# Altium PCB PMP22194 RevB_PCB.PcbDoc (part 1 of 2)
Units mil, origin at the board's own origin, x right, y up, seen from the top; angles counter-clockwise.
Board outline 2100 x 2100 mil, 4 copper layers (Top Layer, Signal Layer 1, Signal Layer 2, Bottom Layer), stack 62.2 mil thick; 70 components, 29 nets, 172 pads, 172 vias.
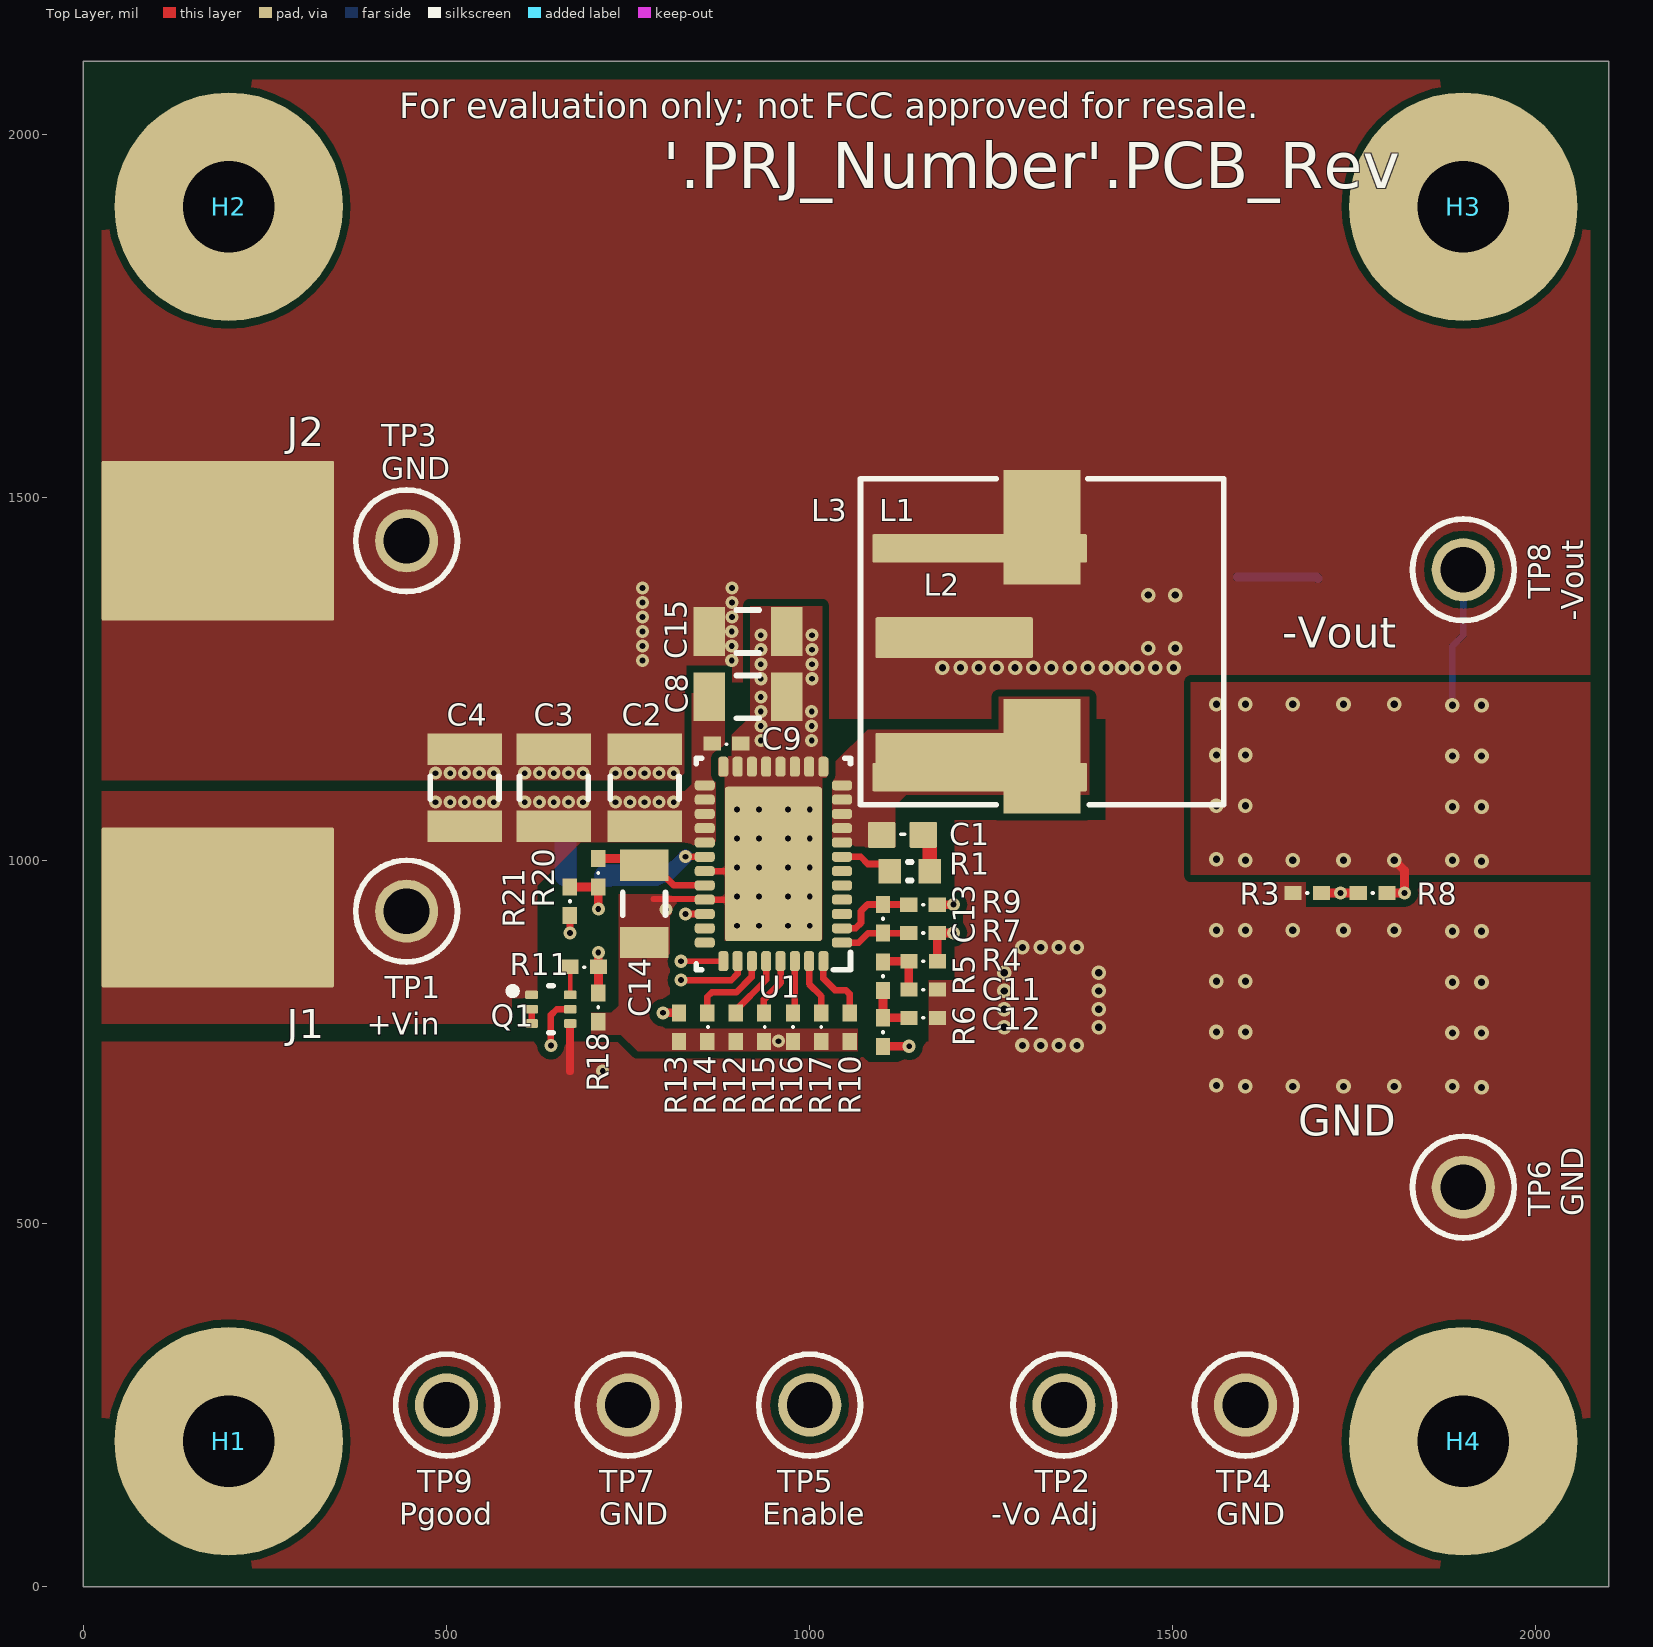
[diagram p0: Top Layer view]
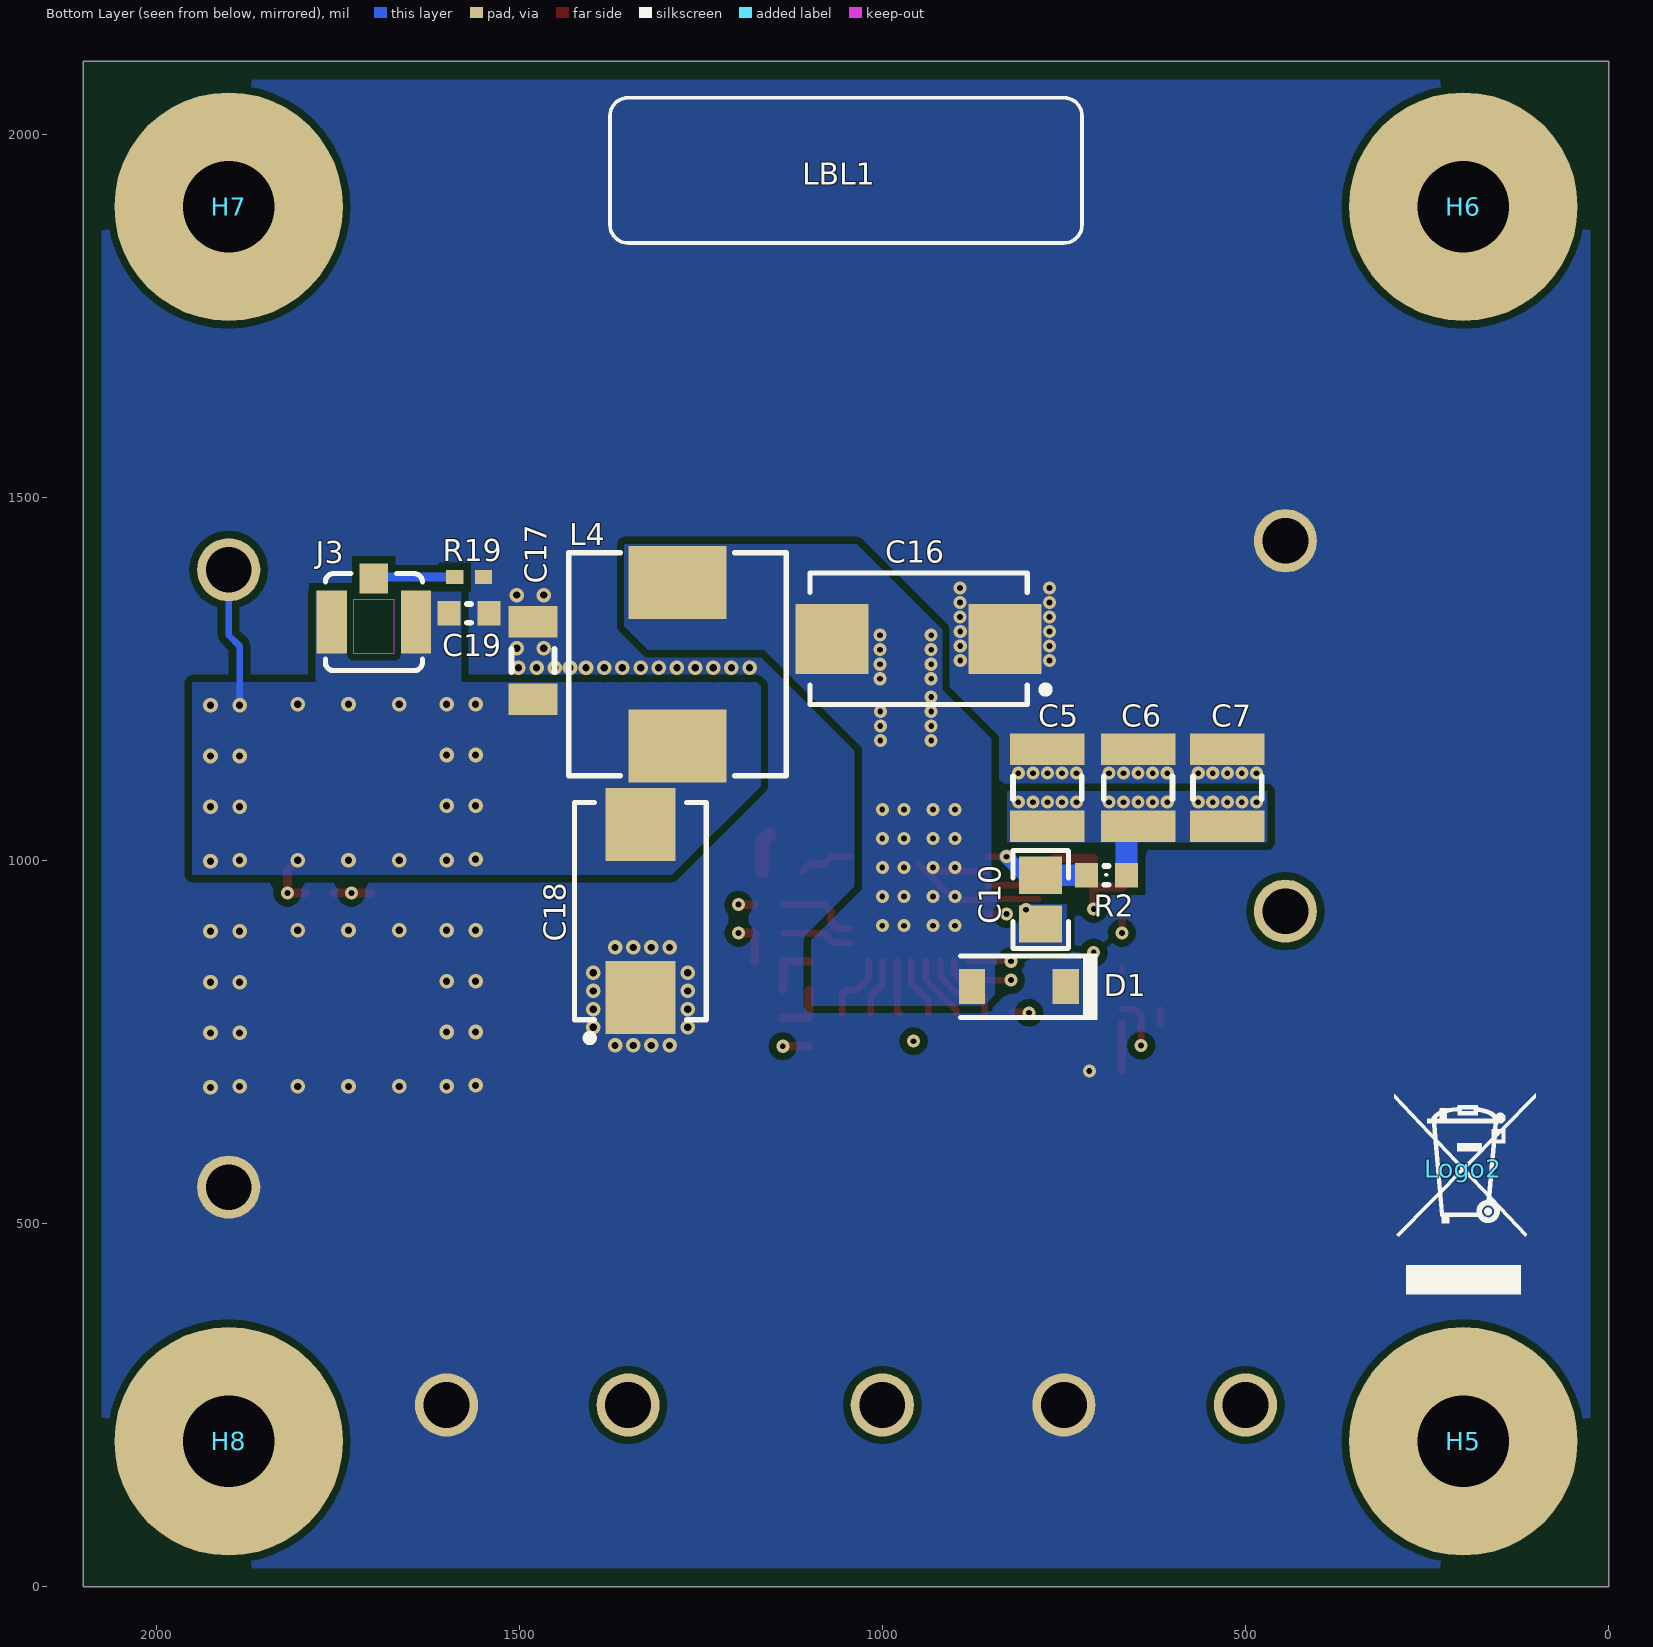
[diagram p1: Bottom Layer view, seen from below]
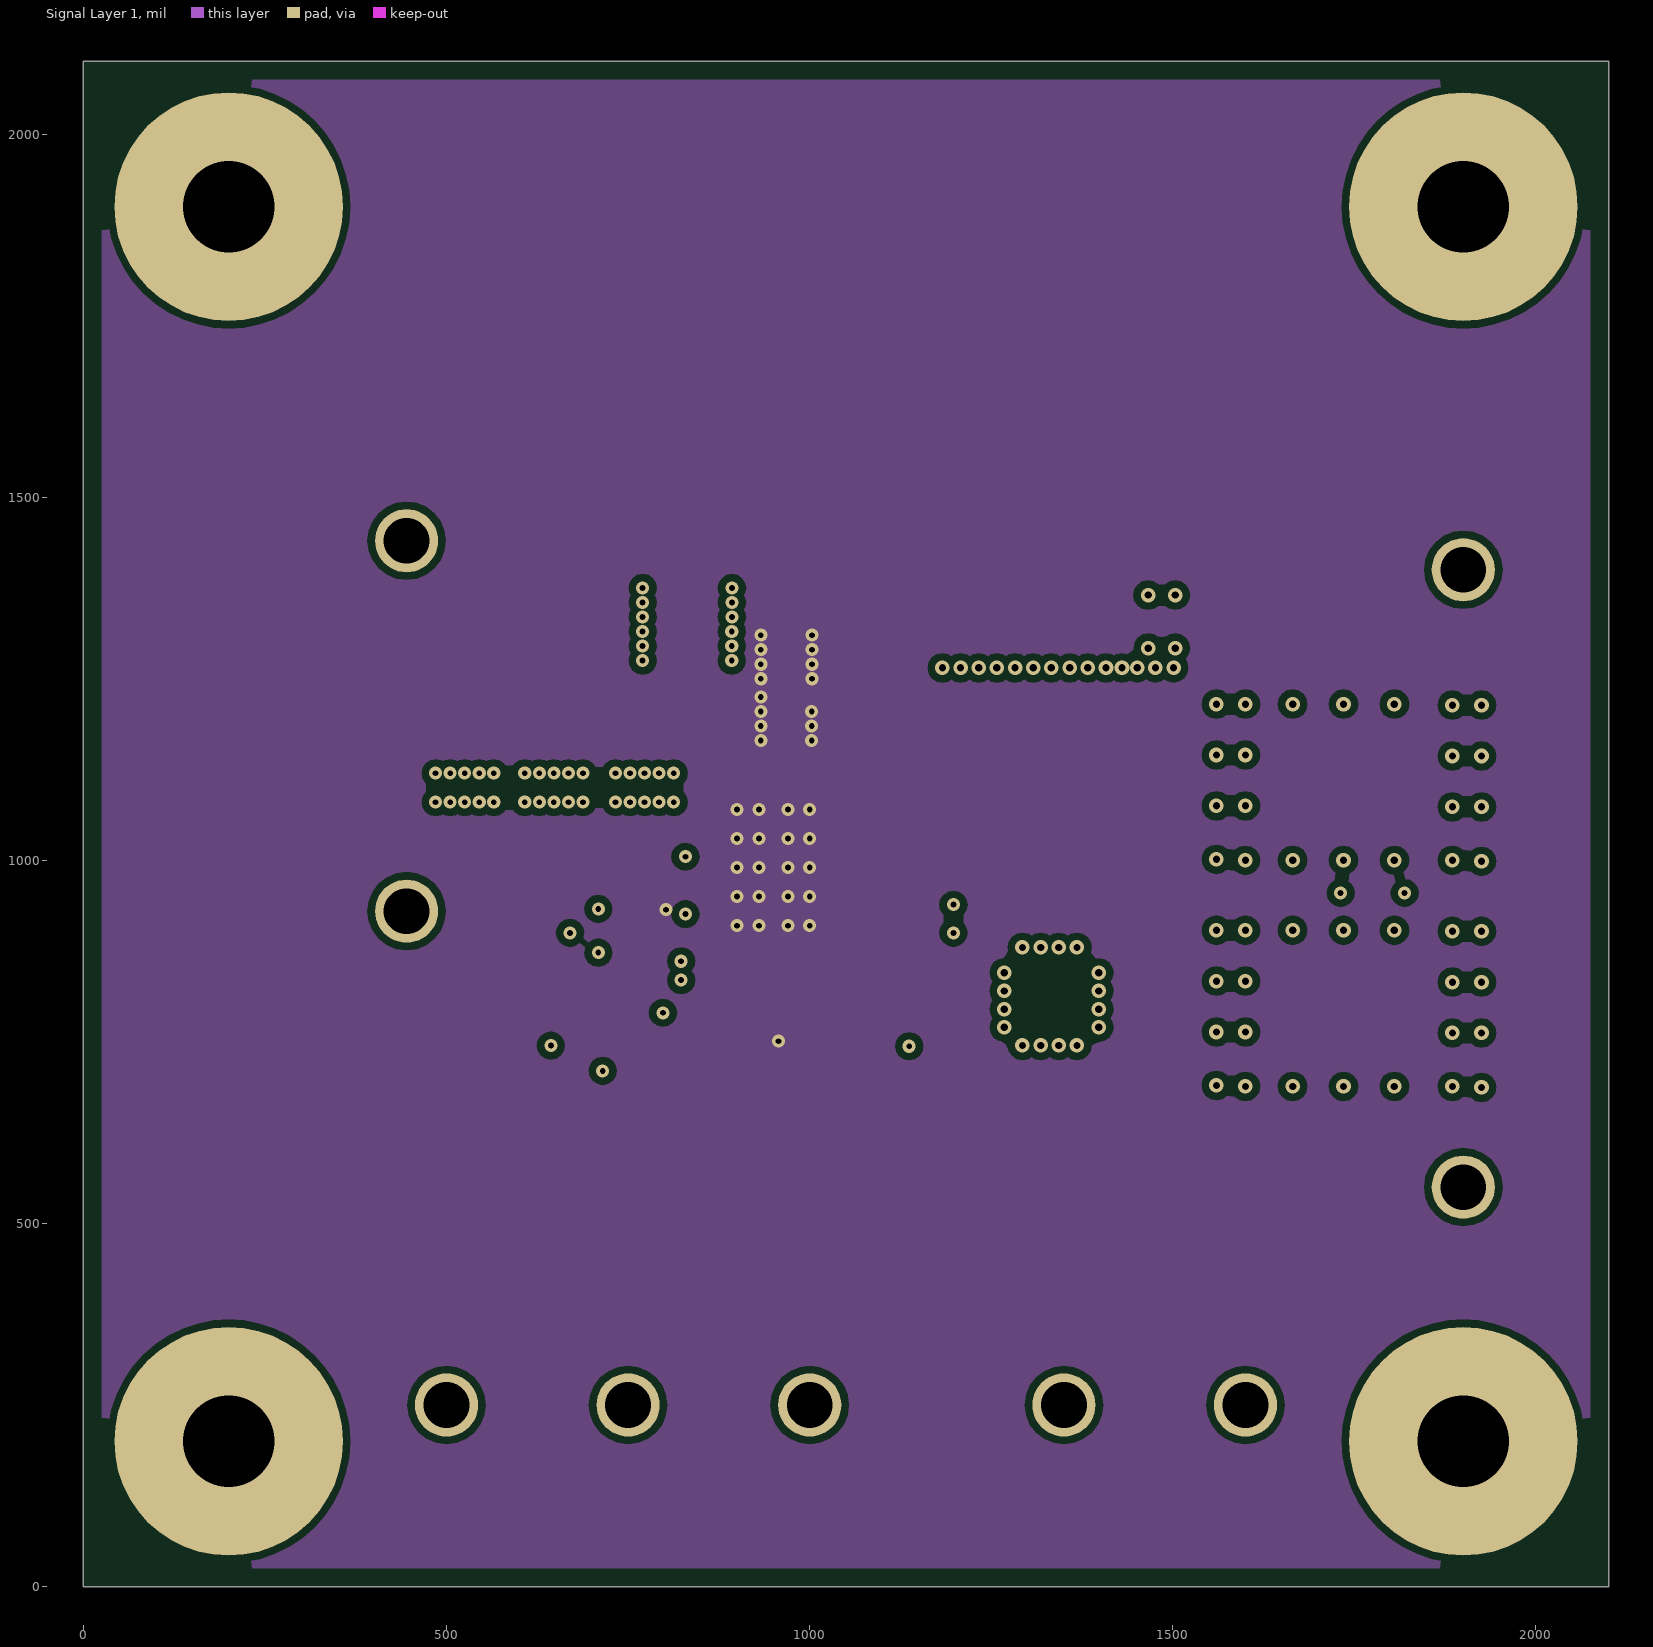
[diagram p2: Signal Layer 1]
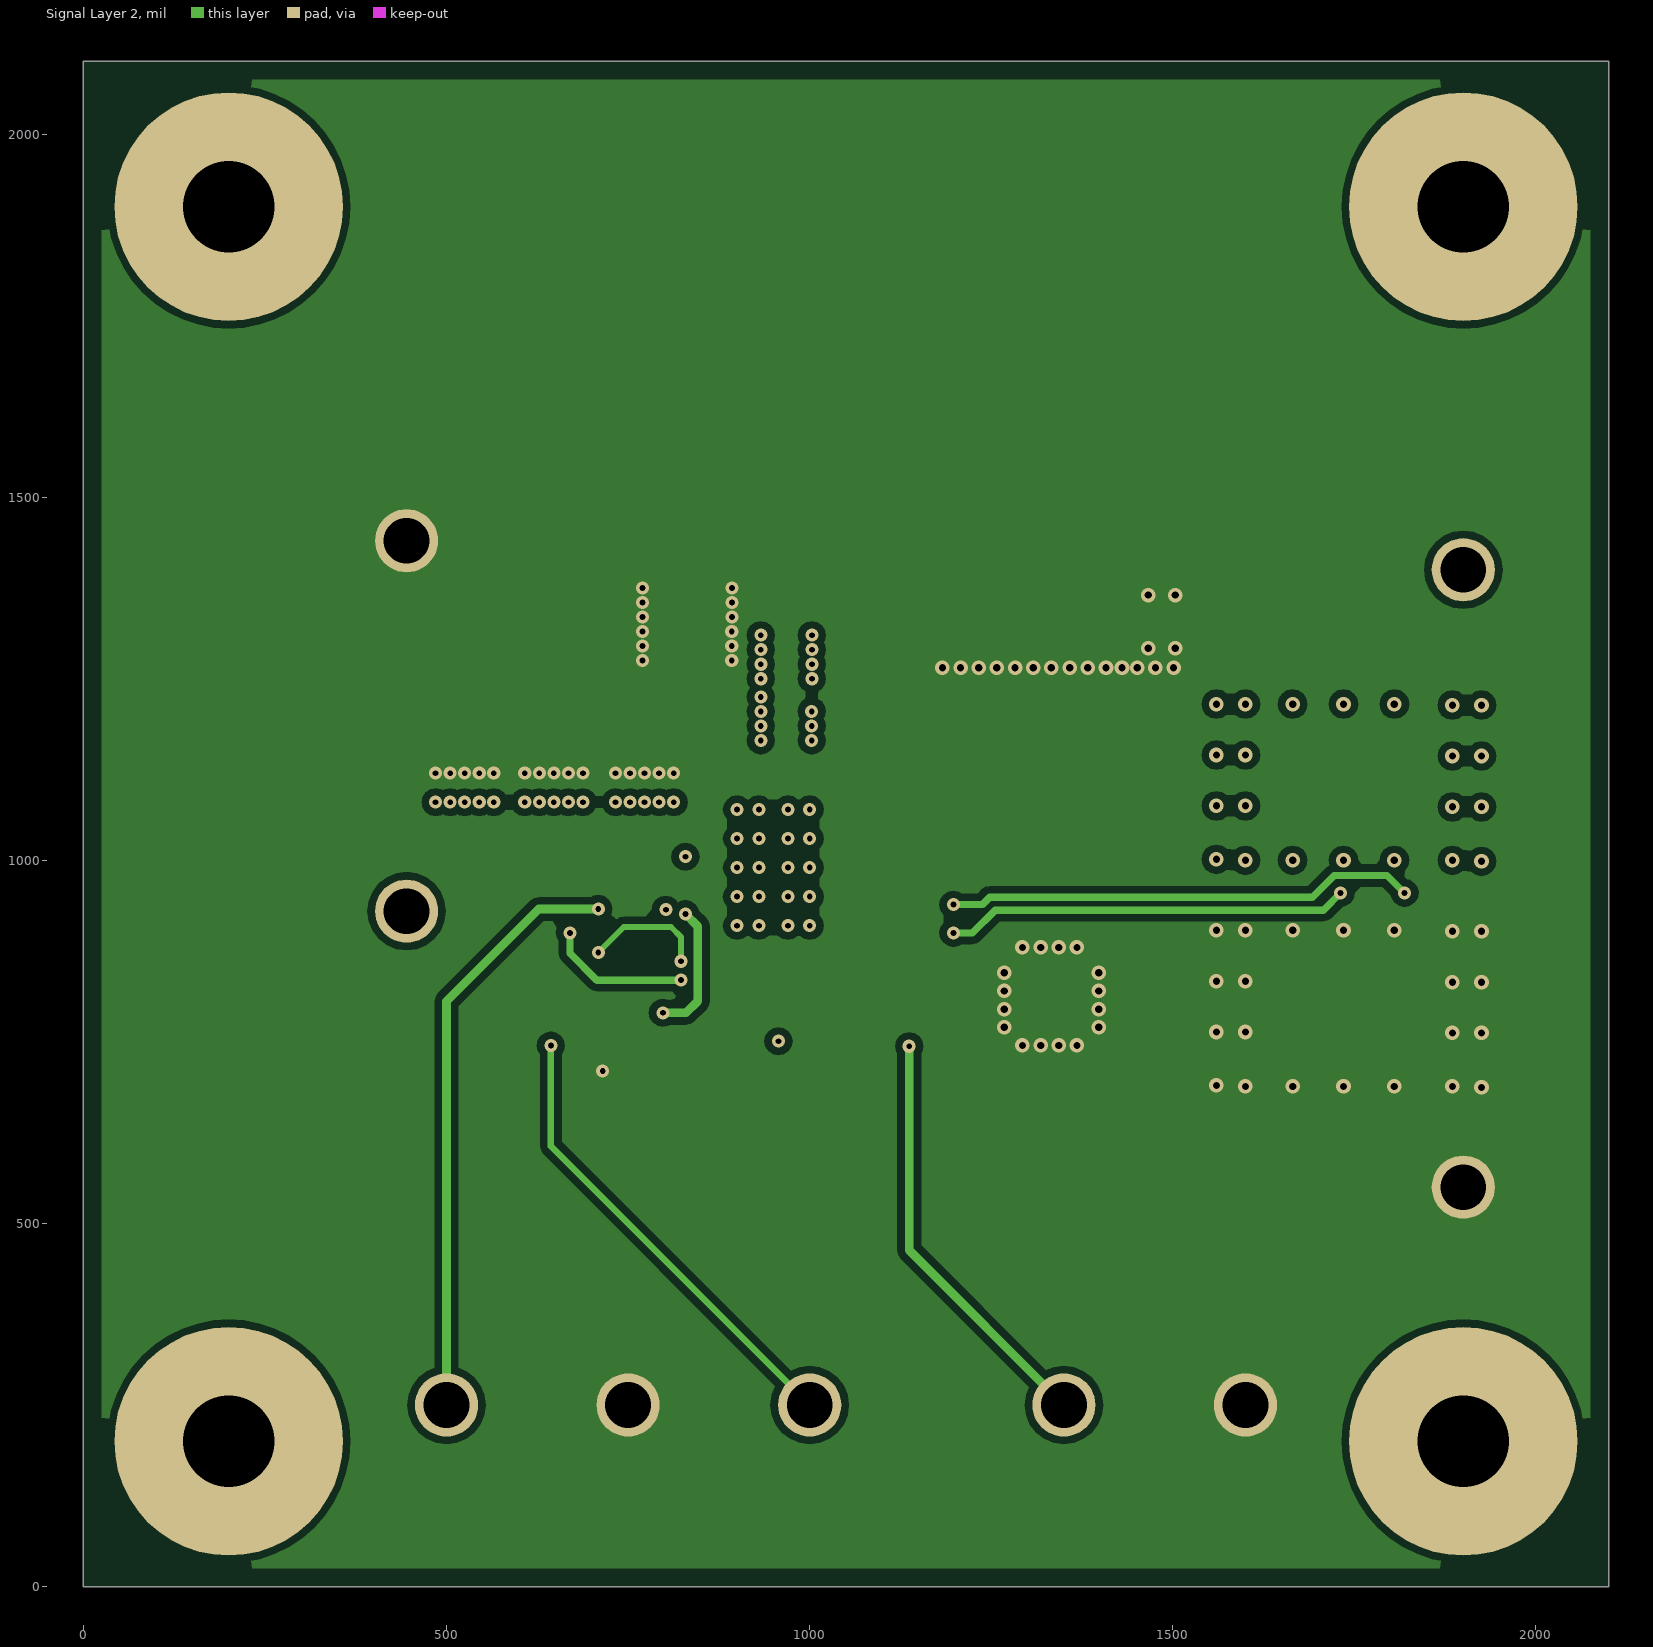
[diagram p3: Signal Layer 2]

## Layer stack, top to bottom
Top Solder: solder mask 0.4, Solder Resist, Dk 3.5
Top Layer: signal copper 2.8
Dielectric 1: dielectric 8, Dk 4.2
Signal Layer 1: signal copper 2.8
Dielectric2: core 35, FR-4, Dk 4.8
Signal Layer 2: signal copper 2.8
Dielectric 3: dielectric 8, Dk 4.2
Bottom Layer: signal copper 2.8
Bottom Solder: solder mask 0.4, Solder Resist, Dk 3.5

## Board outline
0,0 2100,0 2100,2100 0,2100

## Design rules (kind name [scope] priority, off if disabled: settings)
AcuteAngle [All] p1: minimum=4.50000000000000E+0001 checktracksonly=FALSE
AssemblyTestPointUsage [All] p1: valid=2
BoardOutlineClearance BoardOutlineClearance_MountingHoles [OnCopper and InComponentClass('Mounting Holes')] p1: gap=39.37 ignorepadtopadclearanceinfootprint=FALSE
BoardOutlineClearance BoardOutlineClearance_Poly [OnCopper and IsPoly] p2: gap=25 ignorepadtopadclearanceinfootprint=FALSE
BoardOutlineClearance [OnCopper and Not InComponentClass('Logo') and not InComponentClass('FiducialMark') and not InRegion(1000,500,4000,800) and not InPoly] p3: gap=25 ignorepadtopadclearanceinfootprint=FALSE
Clearance Clearance_Keepouts [((IsTrack Or IsArc) And Not InPoly) And IsFree and IsKeepOut vs ((IsTrack Or IsArc) And Not InPoly) And IsFree and IsKeepOut] p1: gap=0 ignorepadtopadclearanceinfootprint=FALSE
Clearance Clearance_Poly [InPolygon] p2: gap=10 ignorepadtopadclearanceinfootprint=TRUE
Clearance Clearance_FiducialMark [IsKeepOut and InComponentClass('FiducialMark') vs IsPad and InComponentClass('FiducialMark')] p3: gap=0 ignorepadtopadclearanceinfootprint=FALSE
Clearance [All] p4: gap=7.87 ignorepadtopadclearanceinfootprint=TRUE
ComponentClearance ComponentClearance_Inductors [(InComponent('L1') OR InComponent('L2') OR InComponent('L3')) vs (InComponent('L1') OR InComponent('L2') OR InComponent('L3'))] p1: gap=-1 collisioncheckmode=3 verticalgap=100000 showdistances=FALSE
ComponentClearance ComponentClearance_MountingHoles_FiducialMarks [InComponentClass('Mounting Holes') vs InComponentClass('FiducialMark')] p2: gap=50 collisioncheckmode=3 verticalgap=10 showdistances=FALSE
ComponentClearance ComponentClearance_Shunt [InComponentClass('Header') vs InComponentClass('Shunt')] p3: gap=0 collisioncheckmode=3 verticalgap=0 showdistances=FALSE
ComponentClearance ComponentClearance_Logo [InComponentClass('Logo')] p4: gap=50 collisioncheckmode=3 verticalgap=10 showdistances=FALSE
ComponentClearance ComponentClearance_ScrewToNut [(HasFootprint('NY PMS 440 0025 PH')) vs (HasFootprint('Keystone_1902C'))] p5: gap=5 collisioncheckmode=3 verticalgap=10 showdistances=FALSE
ComponentClearance ComponentClearance_MountingHoles [InComponentClass('Mounting Holes')] p6: gap=50 collisioncheckmode=3 verticalgap=100000 showdistances=FALSE
ComponentClearance ComponentClearance_SmallPassives [HasFootprint('0201*') or HasFootprint('0402*') or HasFootprint('0508') or HasFootprint('0603*') or HasFootprint('0612') or HasFootprint('0805*') or HasFootprint('0815*') or HasFootprint('0830*') or HasFootprint('1206*') or HasFootprint('1210*') or HasFootprint('1808*') or HasFootprint('1812*') or HasFootprint('1825*') or HasFootprint('2010*') or HasFootprint('2220*') or HasFootprint('2225*') or HasFootprint('2512*') or HasFootprint('2728*') or HasFootprint('3518*') vs HasFootprint('0201*') or HasFootprint('0402*') or HasFootprint('0508') or HasFootprint('0603*') or HasFootprint('0612') or HasFootprint('0805*') or HasFootprint('0815*') or HasFootprint('0830*') or HasFootprint('1206*') or HasFootprint('1210*') or HasFootprint('1808*') or HasFootprint('1812*') or HasFootprint('1825*') or HasFootprint('2010*') or HasFootprint('2220*') or HasFootprint('2225*') or HasFootprint('2512*') or HasFootprint('2728*') or HasFootprint('3518*')] p7: gap=14.96 collisioncheckmode=3 verticalgap=10 showdistances=FALSE
ComponentClearance ComponentClearance_THtoSMT [IsThruComponent vs IsSMTComponent] p8: gap=40 collisioncheckmode=3 verticalgap=30 showdistances=FALSE
ComponentClearance ComponentClearance_THtoTH [IsThruComponent vs IsThruComponent] p9: gap=30 collisioncheckmode=3 verticalgap=30 showdistances=FALSE
ComponentClearance [All] p10: gap=15 collisioncheckmode=3 verticalgap=10 showdistances=FALSE
DiffPairsRouting [All] p1: maxlimit=100 minlimit=10 mostfreqgap=10 toplayer_minwidth=15 toplayer_maxwidth=15 toplayer_prefwidth=15 midlayer1_minwidth=15 midlayer1_maxwidth=15 midlayer1_prefwidth=15 midlayer2_minwidth=15 midlayer2_maxwidth=15 midlayer2_prefwidth=15 bottomlayer_minwidth=15 bottomlayer_maxwidth=15 bottomlayer_prefwidth=15 maxuncoupledlength=1000
FabricationTestPointUsage TestPointUsage [All] p1: valid=2 allowmultiple=FALSE
FabricationTestpoint Testpoint [All] p1: side=3 testpointundercomponent=TRUE minsize=40 maxsize=100 preferedsize=60 minholesize=0 maxholesize=40 preferedholesize=32 testpointgrid=1 allowsidetop=TRUE allowsidebottom=TRUE usegrid=TRUE gridtolerance=0.01
FanoutControl Fanout_LCC [IsLCC] p1: bgadir=Out bgaviamode=Centered fanoutstyle=Auto fanoutdirection=Alternating viagrid=1 // Fanout_LCC (Default Rule)
FanoutControl Fanout_BGA [IsBGA] p2: bgadir=Out bgaviamode=Centered fanoutstyle=Auto fanoutdirection=Alternating viagrid=1 // Fanout_BGA (Default Rule)
FanoutControl Fanout_Default [All] p4: bgadir=Out bgaviamode=Centered fanoutstyle=Auto fanoutdirection=Alternating viagrid=1 // Fanout_Default (Default Rule)
FanoutControl Fanout_Small [(CompPinCount < 5)] p5: bgadir=Out bgaviamode=Centered fanoutstyle=Auto fanoutdirection=OutThenIn viagrid=1 // Fanout_Small (Default Rule)
HoleSize [All] p1: absolutevalues=TRUE maxlimit=251 minlimit=7.87 maxpercent=80.000 minpercent=20.000
MinimumAnnularRing MinimumAnnularRing_ThermalPadVias [IsVia and InAnyComponent] p1: minimumring=5
MinimumAnnularRing [All] p2: minimumring=5
MinimumSolderMaskSliver MinimumSolderMaskSliver_Logo [InComponentClass('Logo') vs InComponentClass('Logo')] p1: minsoldermaskwidth=0.7
MinimumSolderMaskSliver [All] p2: minsoldermaskwidth=3.94
PlaneConnect [All] p1: planeconnectstyle=Direct reliefexpansion=10 reliefentries=4 reliefconductorwidth=10 reliefairgap=10
PolygonConnect [All] p1: connectstyle=Direct reliefconductorwidth=10 reliefentries=4 polygonreliefangle="90 Angle" airgapwidth=10
RoutingVias ThermalPadVias [IsVia and InAnyComponent] p1: holewidth=7.87 width=19.68 viastyle="Through Hole" minholewidth=7.87 minwidth=18 maxholewidth=12.99 maxwidth=24
RoutingVias [All] p2: holewidth=16 width=34 viastyle="Through Hole" minholewidth=7.87 minwidth=18 maxholewidth=40 maxwidth=65
SilkToBoardRegionClearance [Not ((IsComment or IsDesignator) And (Hide <> 'False')) and not InRegion(1000,500,4000,800)] p1:
SilkToSilkClearance SilkToSilkClearance_Pb-FreeLogo [(HasFootprint('Pb-Free_Overlay_Medium') OR HasFootprint('Pb-Free_Overlay_Small')) vs (HasFootprint('Pb-Free_Overlay_Medium') OR HasFootprint('Pb-Free_Overlay_Small'))] p1: silktosilkclearance=0
SilkToSilkClearance [All] p2: silktosilkclearance=3.94
SilkToSolderMaskClearance SilkToComponentPadClearance [(IsPad or IsFill or IsRegion) and InAnycomponent] p1: minsilkscreentomaskgap=3 clearancetoexposedcopper=TRUE
SilkToSolderMaskClearance "Silk to Solder Mask Opening" [All] p2: minsilkscreentomaskgap=3 clearancetoexposedcopper=FALSE
SolderMaskExpansion [All] p1: expansion=1.97
UnRoutedNet [All] p1: checkbadconnections=TRUE
Width [All] p1: maxlimit=100 minlimit=6 preferedwidth=10 checkconnectedcopper=TRUE
14 further rules are at their usual default settings.

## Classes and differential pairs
component class "Mounting Holes": H1 H2 H3 H4
component class "PMP22194 RevB_BlankSheet": C1 C2 C3 C4 C5 C6 C7 C8 C9 C10 C11 C12 C13 C14 C15 C16 C17 C18 C19 D1 J1 J2 J3 L1 L2 L3 L4 Q1 R1 R2 R3 R4 R5 R6 R7 R8 R9 R10 R11 R12 R13 R14 R15 R16 R17 R18 R19 R20 R21 TP1 TP2 TP3 TP4 TP5 TP6 TP7 TP8 TP9 U1
component class "PMP22194 RevB_Hardware": H1 H2 H3 H4 H5 H6 H7 H8 LBL1 Logo1 Logo2
component class Label: LBL1

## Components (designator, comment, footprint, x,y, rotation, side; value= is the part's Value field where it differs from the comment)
C1 "CL10B104KB8NNNC" FP-CL10B104KB8NNNC_0603-IPC_B 1127.72,1035 r0 top
C2 "CL32B226KAJNFNE" 1210_270L 772.72,1100 r90 top value=22uF
C3 "CL32B226KAJNFNE" 1210_270L 647.72,1100 r90 top value=22uF
C4 "CL32B226KAJNFNE" 1210_270L 525,1100 r90 top value=22uF
C5 "CL32B226KAJNFNE" 1210_270L 772.72,1100 r90 bottom value=22uF
C6 "CL32B226KAJNFNE" 1210_270L 647.72,1100 r90 bottom value=22uF
C7 "CL32B226KAJNFNE" 1210_270L 525,1100 r90 bottom value=22uF
C8 "CL31B475KAHNFNE" C1206 915,1225 r0 top value=4.7uF
C9 "GCM155R71H104KE02D" 0402L 885.5,1160.72 r0 top value=0.1uF
C10 "CL21B105KBFNNNG" 0805 782,946 r270 bottom value=1uF
C11 "CL05B224KO5NNNC" 0402L 1156.5,822 r0 top value=0.22uF
C12 "CL05B224KO5NNNC" 0402L 1156.5,783 r0 top value=0.22uF
C13 "DNP" 0402L 1101,919.5 r90 top value=1000pF
C14 "CL31B475KAHNFNE" C1206 772,940 r270 top value=4.7uF
C15 "GRM31CR60J107KE39L" C1206 915,1315 r0 top value=100uF
C16 "2R5TPE470M9" 7343-20 950,1305 r0 bottom value=470uF
C17 "GRM31CR60J107KE39L" C1206 1481,1275.15 r270 bottom value=100uF
C18 "2R5TPE470M9" 7343-20 1333,930.09 r90 bottom value=470uF
C19 "CL10B102KB8NNNC" 0603L 1569,1340 r0 bottom value=1000pF
D1 "MBR0540T1G" SOD-123 812,826 r0 bottom value=40V
H1 "NY PMS 440 0025 PH" "NY PMS 440 0025 PH" 200,200 r0 top
H2 "NY PMS 440 0025 PH" "NY PMS 440 0025 PH" 200,1900 r0 top
H3 "NY PMS 440 0025 PH" "NY PMS 440 0025 PH" 1900,1900 r0 top
H4 "NY PMS 440 0025 PH" "NY PMS 440 0025 PH" 1900,200 r0 top
H5 "1902C" Keystone_1902C 200,200 r180 bottom
H6 "1902C" Keystone_1902C 200,1900 r180 bottom
H7 "1902C" Keystone_1902C 1900,1900 r180 bottom
H8 "1902C" Keystone_1902C 1900,200 r180 bottom
J1 "+Vin" Cinch_108-0902-001 0,935 r0 top
J2 "GND" Cinch_108-0903-001 0,1440 r0 top
J3 "-Vout" CONN_UFL-R-SMT-1 1700,1328 r270 bottom
L1 "XAR7030-501MEB" XAR7030 1234,1272 r90 top value=500nH
L2 "XEL6030-471MEB" XEL6030_320 1199,1227 r90 top value=470nH
L3 "MLC1240-451MLB" MLC1240 1320,1301 r90 top value=450nH
L4 "SLC7649S-360KLB" SLC7649 1282,1270 r270 bottom value=36nH
LBL1 "THT-14-423-10" Label_650x200 1050,1950 r180 bottom
Logo1 "FCC disclaimer" FCC_disclaimer 2405,2160 r0 top
Logo2 "WEEE logo" WEEE_Minimum 200,575 r180 bottom
Q1 "RN4907FE,LF(CT" FP-RN4907FE,LF(CT_SOT-6-MFG 643.72,795 r0 top value=-50/50V
R1 "CRCW06032R00FKEA" 0603L 1137.72,985 r0 top value=2.00
R2 "RC0603JR-070RL" 0603L 691.5,979.28 r180 bottom value=0
R3 "CRCW0402665RFKED" 0402L 1685,955 r180 top value=665
R4 "CRCW04021K58FKED" 0402L 1156.22,861 r180 top value=1.58k
R5 "CRCW04021K58FKED" 0402L 1101,840.5 r270 top value=1.58k
R6 "CRCW04021K58FKED" 0402L 1101,763.5 r270 top value=1.58k
R7 "RC0402JR-070RL" 0402L 1156,900 r180 top value=0
R8 "CRCW0402249KFKED" 0402L 1775,955 r180 top value=249k
R9 "RC0402JR-070RL" 0402L 1156,939 r180 top value=0
R10 "RC0402JR-070RL" 0402L 1055,770 r90 top value=0
R11 "CRCW0402100KJNED" 0402L 689.5,853.28 r180 top value=100k
R12 "RC0402JR-070RL" 0402L 898,770 r90 top value=0
R13 "RC0402JR-070RL" 0402L 820,770 r90 top value=0
R14 "DNP" 0402L 859,770 r90 top value=0
R15 "CRCW0402475KFKED" 0402L 937,770 r270 top value=475k
R16 "CRCW0402130KFKED" 0402L 977,770 r90 top value=130k
R17 "RC0402JR-070RL" 0402L 1016,770 r90 top value=0
R18 "CRCW040251K0JNED" 0402L 708.72,797.5 r90 top value=51k
R19 "RC0402FR-0749R9L" 0402L 1569,1390 r0 bottom value=49.9
R20 "CRCW0402100KFKED" 0402L 709,982.72 r90 top value=100k
R21 "CRCW040212K1FKED" 0402L 669.72,943.5 r90 top value=12.1k
TP1 "+Vin" Keystone5010 445,930 r0 top
TP2 "-Vo Adj" Keystone5012 1350,250 r0 top
TP3 "GND" Keystone5011 445,1440 r0 top
TP4 "GND" Keystone5011 1600,250 r0 top
TP5 "Enable" Keystone5012 1000,250 r0 top
TP6 "GND" Keystone5011 1900,550 r90 top
TP7 "GND" Keystone5011 750,250 r0 top
TP8 "-Vout" Keystone5013 1900,1400 r90 top
TP9 "Pgood" Keystone5012 500,250 r0 top
U1 "TPS543B20RVFT" RVF0040A_SMD_NV 950,995 r180 top

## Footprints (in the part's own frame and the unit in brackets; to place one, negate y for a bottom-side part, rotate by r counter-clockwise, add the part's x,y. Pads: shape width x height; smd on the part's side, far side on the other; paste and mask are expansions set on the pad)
0402L [mm] "0402 from SM-752 data"
  rect 0.6x0.5 smd: 1(-0.5,0) 2(0.5,0)
  body extent -0.55,-0.3 0.55,0.3, height 0.6
0603L [mm] "0603 from SM-752 data"
  rect 0.8x0.85 smd: 1(-0.7,0) 2(0.7,0)
  silkscreen extent -0.07,-0.33 0.07,0.33, body extent -0.87,-0.47 0.87,0.47, height 1
0805 [mm] "0805 from SM-752 data"
  rect 1.3x1.5 smd: 1(-0.85,0) 2(0.85,0)
  silkscreen extent -1.72,-0.97 1.72,0.97, body extent -1.1,-0.72 1.1,0.72, height 1.45
1210_270L [mm] "1210"
  rect 1.1x2.6 smd: 1(-1.35,0) 2(1.35,0)
  silkscreen extent -0.4,-1.2 0.4,1.2, body extent -1.7,-1.35 1.7,1.35, height 2.7
7343-20 [mm] "Medium density IPC, based on Kemet case V from T495 datasheet"
  rect 2.55x2.45 smd: 1(-3.025,0) 2(3.025,0)
  silkscreen extent -4.56,-2.3 3.8,2.3, body extent -3.8,-2.3 3.8,2.3, height 2
C1206 [mm] "Chip Capacitor, Body 3.2x1.6mm, IPC High Density"
  rect 1.1x1.7 smd: 1(-1.35,0) 2(1.35,0)
  silkscreen extent -0.4,-0.75 0.4,0.75, body extent -1.7,-0.9 1.7,0.9, height 1.3
Cinch_108-0902-001 [mil] "Banana Jack Insul Nylon Red, TH"
  rrect2% 320x220 smd: 1(185,0)
  body extent -666,-219 272,219, height 232
Cinch_108-0903-001 [mil] "Banana Jack Insul Nylon Black, TH"
  rrect2% 320x220 smd: 1(185,0)
  body extent -666,-219 272,219, height 232
CONN_UFL-R-SMT-1 [mm] "Hirose recommended land pattern http://www.hirose.co.jp/cataloge_hp/e32119372.pdf 2009.2"
  rect 1.05x1 smd paste-0.1 mask-0.1: 1(-1.525,0)
  rect 2.2x1.05 smd paste-2 mask-2: 2(0,1.475) 3(0,-1.475)
  rect 2x0.9 on Bottom Paste: 2(0,1.5) 3(0,-1.5)
  rect 2x0.9 on Bottom Solder: 2(0,1.5) 3(0,-1.5)
  Top Layer keep-out region: -0.8,0.7 1.1,0.7 1.1,-0.7 -0.8,-0.7
  silkscreen extent -1.7,-1.7 1.7,1.7, body extent -1.55,-1.5 1.55,1.5, height 1.27
FCC_disclaimer [mil]
FP-CL10B104KB8NNNC_0603-IPC_B [mil]
  rrect11% 37.72x35.91 smd paste+0 mask+0: 1(-28.62,0) 2(28.62,0)
  body extent -57,-28 57,28, height 10
FP-RN4907FE,LF(CT_SOT-6-MFG [mm]
  rrect33% 0.45x0.3 smd paste+0 mask+0: 1(-0.675,0.5) 2(-0.675,0) 3(-0.675,-0.5) 4(0.675,-0.5) 5(0.675,0) 6(0.675,0.5)
  silkscreen extent -1.46,-0.82 0.08,0.82, body extent -1,-0.92 1,0.92, height 0.25
Keystone5010 [mil] "Keystone Multipurpose loops"
  round 87 hole 63: 1(0,0)
  silkscreen extent -70,-70 70,70, body extent -63,-63 63,62, height 319
Keystone5011 [mil] "Keystone Multipurpose loops"
  round 87 hole 63: 1(0,0)
  silkscreen extent -70,-70 70,70, body extent -63,-63 63,62, height 319
Keystone5012 [mil] "Keystone Multipurpose loops"
  round 87 hole 63: 1(0,0)
  silkscreen extent -70,-70 70,70, body extent -63,-63 63,62, height 319
Keystone5013 [mil] "Keystone Multipurpose loops"
  round 87 hole 63: 1(0,0)
  silkscreen extent -70,-70 70,70, body extent -63,-63 63,62, height 319
Keystone_1902C [mil] "Hex Standoff, 4-40 threaded, nylon"
  round 1 on Mech4: 0(0,0)
  body extent -145,-126 146,126, height 501
Label_650x200 [mil] "Thermal Transfer Label"
  round 1 on Mech14: 0(0,0)
  silkscreen extent -325,-100 325,100, body extent -325,-100 325,100, height 1
MLC1240 [mm] "COILCRAFT"
  rect 4x2.7 smd: 1(-4,0) 2(4,0)
  silkscreen extent -5.7,-6.35 5.7,6.35, body extent -5.6,-6.25 5.6,6.25, height 4.1
"NY PMS 440 0025 PH" [mm] "4-40 nylon screw and mounting hole"
  round 8 hole 3.2: 1(0,0)
  body extent -3.31,-3.3 3.3,3.3, height 2.69
RVF0040A_SMD_NV [mm] "LQFN-CLIP"
  rrect57% 0.7x0.35 smd paste-0.05 mask-0.05: 1(-2.4,2.75) 2(-2.4,2.25) 3(-2.4,1.75) 4(-2.4,1.25) 5(-2.4,0.75) 6(-2.4,0.25) 7(-2.4,-0.25) 8(-2.4,-0.75) 9(-2.4,-1.25) 10(-2.4,-1.75) 11(-2.4,-2.25) 12(-2.4,-2.75) 21(2.4,-2.75) 22(2.4,-2.25) 23(2.4,-1.75) 24(2.4,-1.25) 25(2.4,-0.75) 26(2.4,-0.25) 27(2.4,0.25) 28(2.4,0.75) 29(2.4,1.25) 30(2.4,1.75) 31(2.4,2.25) 32(2.4,2.75)
  rrect57% 0.35x0.7 smd paste-0.05 mask-0.05: 13(-1.75,-3.4) 14(-1.25,-3.4) 15(-0.75,-3.4) 16(-0.25,-3.4) 17(0.25,-3.4) 18(0.75,-3.4) 19(1.25,-3.4) 20(1.75,-3.4) 33(1.75,3.4) 34(1.25,3.4) 35(0.75,3.4) 36(0.25,3.4) 37(-0.25,3.4) 38(-0.75,3.4) 39(-1.25,3.4) 40(-1.75,3.4)
  rrect9% 1.43x1.08 on Top Paste: 41(-0.815,1.92) 41(-0.815,-0.64) 41(-0.815,0.64) 41(-0.815,-1.92) 41(0.815,1.92) 41(0.815,-0.64) 41(0.815,0.64) 41(0.815,-1.92)
  rrect6% 3.4x5.4 smd paste-2 mask-0.05: 41(0,0)
  silkscreen extent -2.7,-3.7 2.7,3.7, body extent -2.5,-3.5 2.5,3.5, height 1.52
SLC7649 [mm] "COILCRAFT"
  rect 2.54x3.43 smd: 1(-2.86,0) 2(2.86,0)
  silkscreen extent -3.9,-3.8 3.9,3.8, body extent -3.81,-3.74 3.81,3.74, height 4.96
SOD-123 [mm] "On Semi recommended land pattern"
  rect 0.915x1.22 smd: 1(-1.637,0) 2(1.637,0)
  silkscreen extent -2.74,-1.17 2.03,1.17, body extent -1.93,-0.9 1.93,0.9, height 1.35
WEEE_Minimum [mil] "WEEElie bin"
  silkscreen extent -95,-172 99,104
XAR7030 [mm] "SMD, 2-Leads, Body 8.5x8.5mm"
  rrect10% 1x7.5 smd: 1(-4,0) 2(4,0)
  body extent -4.12,-4.25 4.13,4.25, height 6.25
XEL6030_320 [mm] "SMD, 2-Leads, Body 66.36x6.56 mm"
  rrect7% 1.43x5.5 smd: 1(-2.02,0) 2(2.02,0)
  body extent -3.28,-3.38 3.28,3.38, height 3.2

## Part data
C1: library part CMP-0087079-2, "CAP CER 0.1UF 50V X7R 0603", Manufacturer=Samsung, TempCo=15%, Tolerance_%=10%
C2 C3 C4 C5 C6 C7: library part CMP-0080066-1, "CAP, CERM, 22 µF, 25 V,+/- 10%, X7R, 1210", Cap_Case=1210, Manufacturer="Samsung Electro-Mechanics", Supplier Part Number 1=1276-3391-1-ND, TempCo=X7R, Tolerance_%=10%, Value2=25V, ValueDisplayed=22µF
C8 C14: library part Capacitor, "CAP, CERM, 4.7uF, 25V, X7R, 10%, 1206", Alternate Manufacturer=-, Manufacturer=Samsung, Value1=25V
C9: library part CMP-0006356-2, "CAP, CERM, 0.1 uF, 50 V, +/- 10%, X7R, AEC-Q200 Grade 1, 0402", Cap_Case=0402, Manufacturer=MuRata, Supplier Part Number 1=490-10672-1-ND, TempCo=X7R, Tolerance_%=10%, Value1=Unknown, Value2=50V, ValueDisplayed=0.1uF
C10: library part Capacitor, "CAP, CERM, 1uF, 50V, X7R, 10%, 0805", Alternate Manufacturer=-, Manufacturer=Samsung, Value1=50V
C11 C12: library part CMP-0860563-1, "CAP, CERM, 0.22 µF, 16 V,+/- 10%, X7R, 0402", Cap_Case=0402, Manufacturer="Samsung Electro-Mechanics", TempCo=X7R, Tolerance_%=10%, Value2=16V, ValueDisplayed=0.22µF
C13: library part CMP-0006412-2, "CAP, CERM, 1000 pF, 50 V, +/- 5%, C0G/NP0, 0402", Cap_Case=0402, Manufacturer=MuRata, PartNumber=GRM1555C1H102JA01D, Supplier Part Number 1=490-3244-1-ND, TempCo=C0G/NP0, Tolerance_%=5%, Value1=Unknown, Value2=50V, ValueDisplayed=1000pF
C15 C17: library part Capacitor, "CAP, CERM, 100uF, 6.3V, X5R, 10%, 1206", Alternate Manufacturer=-, Manufacturer=Murata, Value1=6.3V
C16 C18: library part Capacitor_Polarized, "CAP, Molded Tantalum Polymer, 470uF, 2.5V, +/-20%, 9mOhm ESR, SMT", Alternate Manufacturer=-, Manufacturer=Panasonic, Value1=2.5V
C19: library part CMP-0084856-1, "CAP, CERM, 1000 pF, 50 V,+/- 10%, X7R, 0603", Cap_Case=0603, Manufacturer="Samsung Electro-Mechanics", TempCo=X7R, Tolerance_%=10%, Value2=50V, ValueDisplayed=1000pF
D1: library part CMP-0028526-2, "Diode, Schottky, 40 V, 0.5 A, SOD-123", Manufacturer="ON Semiconductor", Value1=0.5A, Value2=0.51V
H1 H2 H3 H4: library part CMP-0003617-1, "Machine Screw, Round, #4-40 x 1/4, Nylon, Philips panhead", Manufacturer="B&F Fastener Supply", Supplier Part Number 1=H542-ND
H5 H6 H7 H8: library part CMP-0003610-1, "Standoff, Hex, 0.5\"L #4-40 Nylon", Manufacturer=Keystone, Supplier Part Number 1=36-1902C-ND
J1: library part CMP-0079575-1, "Banana Jack Insul Nylon Red, TH", Color=Red, Current_A=15A, Manufacturer="Cinch Connectivity", PartNumber=108-0902-001, Supplier Part Number 1=J151-ND
J2: library part CMP-0079574-1, "Banana Jack Insul Nylon Black, TH", Color=Black, Current_A=15A, Manufacturer="Cinch Connectivity", PartNumber=108-0903-001, Supplier Part Number 1=J152-ND
J3: library part CMP-0075320-1, "Receptacle, Ultra Miniature Coaxial, Male Pin, 50 ohm, SMT", Color=Beige, Manufacturer="Hirose Electric Co. Ltd.", PartNumber=U.FL-R-SMT-1(01), Supplier Part Number 1=H122041-ND
L1: library part CMP-0084759-1, "Inductor, Shielded, Composite, 500 nH, 17.5 A, 0.0033 ohm, SMD", Manufacturer=Coilcraft, Value1="0.0033 ohm", Value2=17.5A, ValueDisplayed=500nH
L2: library part CMP-0061103-3, "Inductor, Shielded, Composite, 470 nH, 22.3 A, 0.00331 ohm, AEC-Q200 Grade 1, SMD", Manufacturer=Coilcraft, Value1="0.00331 ohm", Value2=22.3A, ValueDisplayed=470nH
L3: library part CMP-0060545-1, "Inductor, Square Pot Core, Powdered Iron, 450 nH, 19.8 A, 0.00173 ohm, SMD", Manufacturer=Coilcraft, Value1="0.00173 ohm", Value2=19.8A, ValueDisplayed=450nH
L4: library part CMP-0060903-1, "Inductor, Shielded, Ferrite, 36 nH, 39 A, 0.00017 ohm, SMD", Manufacturer=Coilcraft, Value1="0.00017 ohm", Value2=39A, ValueDisplayed=36nH
LBL1: library part CMP-0003625-1, "Thermal Transfer Printable Labels, 0.650\" W x 0.200\" H - 10,000 per roll", Manufacturer=Brady, Supplier Part Number 1=97C5133
Logo1: library part CMP-0074847-1, "FCC_disclaimer"
Logo2: library part CMP-0074769-1
Q1: library part CMP-0086797-1, "Bipolar Transistors - Pre-Biased Bias Resistor Built-in transistor", Manufacturer=Toshiba
R1: library part CMP-0022302-4, "RES, 2.00, 1%, 0.1 W, AEC-Q200 Grade 0, 0603", Manufacturer=Vishay-Dale, Power_W=100mW, Supplier Part Number 1=541-2.00HHCT-ND, TempCo="100 ppm/C", Tolerance_%=1%, Value2=0.1W, Value_Code=2R00, ValueDisplayed=2.00
R2: library part CMP-0025885-5, "RES, 0, 5%, 0.1 W, 0603", Manufacturer=Yageo, Power_W=100mW, Supplier Part Number 1=311-0.0GRCT-ND, TempCo="200 ppm/C", Tolerance_%=5%, Value2=0.1W, Value_Code=0000, ValueDisplayed=0
R3: library part CMP-0026501-2, "RES, 665, 1%, 0.063 W, AEC-Q200 Grade 0, 0402", Manufacturer=Vishay-Dale, Power_W=63mW, Supplier Part Number 1=541-665LCT-ND, TempCo="100 ppm/C", Tolerance_%=1%, Value2=0.063W, Value_Code=665R, ValueDisplayed=665
R4 R5 R6: library part CMP-0026090-3, "RES, 1.58 k, 1%, 0.063 W, AEC-Q200 Grade 0, 0402", Manufacturer=Vishay-Dale, Power_W=63mW, Supplier Part Number 1=541-1.58KLCT-ND, TempCo="100 ppm/C", Tolerance_%=1%, Value2=0.063W, Value_Code=1k58, ValueDisplayed=1.58k
R7 R9 R10 R12 R13 R17: library part CMP-0027004-2, "RES, 0, 5%, 0.063 W, 0402", Manufacturer="Yageo America", Power_W=63mW, Supplier Part Number 1=311-0.0JRCT-ND, TempCo="200 ppm/C", Tolerance_%=5%, Value2=0.063W, Value_Code=0000, ValueDisplayed=0
R8: library part CMP-0026193-2, "RES, 249 k, 1%, 0.063 W, AEC-Q200 Grade 0, 0402", Manufacturer=Vishay-Dale, Power_W=63mW, Supplier Part Number 1=541-249KLCT-ND, TempCo="100 ppm/C", Tolerance_%=1%, Value2=0.063W, Value_Code=249k
R11: library part CMP-0026823-3, "RES, 100 k, 5%, 0.063 W, AEC-Q200 Grade 0, 0402", Manufacturer=Vishay-Dale, Power_W=63mW, Supplier Part Number 1=541-100KJCT-ND, TempCo="200 ppm/C", Tolerance_%=5%, Value2=0.063W, Value_Code=100k
R14: library part CMP-0027004-2, "RES, 0, 5%, 0.063 W, 0402", Manufacturer="Yageo America", PartNumber=RC0402JR-070RL, Power_W=63mW, Supplier Part Number 1=311-0.0JRCT-ND, TempCo="200 ppm/C", Tolerance_%=5%, Value2=0.063W, Value_Code=0000, ValueDisplayed=0
R15: library part CMP-0026393-2, "RES, 475 k, 1%, 0.063 W, AEC-Q200 Grade 0, 0402", Manufacturer=Vishay-Dale, Power_W=63mW, Supplier Part Number 1=541-475KLCT-ND, TempCo="100 ppm/C", Tolerance_%=1%, Value2=0.063W, Value_Code=475k
R16: library part CMP-0025997-3, "RES, 130 k, 1%, 0.063 W, AEC-Q200 Grade 0, 0402", Manufacturer=Vishay-Dale, Power_W=63mW, Supplier Part Number 1=541-130KLCT-ND, TempCo="100 ppm/C", Tolerance_%=1%, Value2=0.063W, Value_Code=130k
R18: library part CMP-0026945-3, "RES, 51 k, 5%, 0.063 W, AEC-Q200 Grade 0, 0402", Manufacturer=Vishay-Dale, Power_W=63mW, Supplier Part Number 1=541-51KJCT-ND, TempCo="200 ppm/C", Tolerance_%=5%, Value2=0.063W, Value_Code=51k0, ValueDisplayed=51k
R19: library part CMP-0026738-1, "RES, 49.9, 1%, 0.063 W, 0402", Manufacturer="Yageo America", Power_W=63mW, Supplier Part Number 1=311-49.9LRCT-ND, TempCo="100 ppm/C", Tolerance_%=1%, Value2=0.063W, Value_Code=49R9, ValueDisplayed=49.9
R20: library part CMP-0025950-3, "RES, 100 k, 1%, 0.063 W, AEC-Q200 Grade 0, 0402", Manufacturer=Vishay-Dale, Power_W=63mW, Supplier Part Number 1=541-100KLCT-ND, TempCo="100 ppm/C", Tolerance_%=1%, Value2=0.063W, Value_Code=100k
R21: library part CMP-0025991-3, "RES, 12.1 k, 1%, 0.063 W, AEC-Q200 Grade 0, 0402", Manufacturer=Vishay-Dale, Power_W=63mW, Supplier Part Number 1=541-12.1KLCT-ND, TempCo="100 ppm/C", Tolerance_%=1%, Value2=0.063W, Value_Code=12k1, ValueDisplayed=12.1k
TP1: library part CMP-0055147-1, "Test Point, Multipurpose, Red, TH", Color=Red, Manufacturer=Keystone, PartNumber=5010, Supplier Part Number 1=36-5010-ND
TP2 TP5 TP9: library part CMP-0055149-1, "Test Point, Multipurpose, White, TH", Color=White, Manufacturer=Keystone, PartNumber=5012, Supplier Part Number 1=36-5012-ND
TP3 TP4 TP6 TP7: library part CMP-0055148-1, "Test Point, Multipurpose, Black, TH", Color=Black, Manufacturer=Keystone, PartNumber=5011, Supplier Part Number 1=36-5011-ND
TP8: library part CMP-0055150-1, "Test Point, Multipurpose, Orange, TH", Color=Orange, Manufacturer=Keystone, PartNumber=5013, Supplier Part Number 1=36-5013-ND
U1: library part CMP-0014068-8, "4-19Vin 25A Stackable Synchronous Step-down SWIFT(TM) Converter w/ Adaptive Internal Compensation, RVF0040A (LQFN-CLIP-40)", Alternate Manufacturer="Texas Instruments", Alternate PartNumber=TPS543B20RVFR, Operating Temperature Range="-40 to 125 C", Rating=Catalog

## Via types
v1: diameter 20, hole 10, Top Layer to Bottom Layer, tented both sides, 78 vias
v2: diameter 18, hole 8, Top Layer to Bottom Layer, tented both sides, 72 vias
v3: diameter 18, hole 8, Top Layer to Bottom Layer, 20 vias
v4: diameter 18, hole 8, Top Layer to Bottom Layer, tented top, 2 vias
